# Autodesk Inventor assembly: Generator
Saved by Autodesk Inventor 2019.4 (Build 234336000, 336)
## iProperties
Created: 2020-04
Part Number: Generator
Document SubType Name: Assembly
Designer: Administrator
Title: Generator v12
Author: Administrator
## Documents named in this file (2)
- c:\worker\convert-fusion-r03\tmp\job-1\48\output\files\ccae6ef3-9f0e-42ff-b199-3a2c6474057a\Generator v12.iam
- c:\worker\convert-fusion-r03\tmp\job-1\48\output\files\ccae6ef3-9f0e-42ff-b199-3a2c6474057a\Generator.ipt
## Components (1 placed, 1 different names)
1. Generator:1
